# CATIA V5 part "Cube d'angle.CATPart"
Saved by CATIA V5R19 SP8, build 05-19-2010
Part number: Cube d'angle
Bounding box of the stored display mesh (mm): x -5 to 5, y -5 to 5, z -5 to 5
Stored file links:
  D:\Documents\1_Travail\1 - ac-limoges.fr\ac-limoges.fr\Emmanuel Maynard - STI2D_Turgot\1 - IT-I2D\Activités_IT_Première\IT_3_Abris_bus\Maquettes numériques\Abribus_eleve\Cube d'angle.CATPart
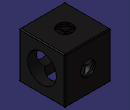
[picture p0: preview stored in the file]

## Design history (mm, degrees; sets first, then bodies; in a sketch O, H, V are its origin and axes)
AxisSystem1: origin (0, 0, 0), X (1, 0, 0), Y (0, 1, 0), Z (0, 0, 1)
Body1 (main body)
  Sketch1 on YZ plane of AxisSystem1, origin (0, 0, 0), H (0, 1, 0), V (0, 0, 1)
    line L1 (5, 5) -> (5, -5)
    line L2 (5, -5) -> (-5, -5)
    line L3 (-5, -5) -> (-5, 5)
    line L4 (-5, 5) -> (5, 5)
    length L2 = 10
    distance L2 L4 = 10
    vertical: L1 V, L3 V
    horizontal: L2 H, L4 H
    equidistance: L1 L3 O, L2 L4 O
  Pad1: profile Sketch1, direction (1, 0, 0), length 5, mirrored extent
  Fillet1: radius 0.2, on face of Pad1 from Sketch1.L3; face of Pad1 from Sketch1.L1; face of Pad1 from Sketch1.L2; start face of Pad1; face of Pad1 from Sketch1.L4
  Sketch2 on end face of Pad1, origin (5, 1.132, -0.2523), H (0, 1, 0), V (0, 0, 1)
    point P1 (-1.132, 0.2523)
    reference projected point E1 (-1.132, 0.2523) from vertex [YZ plane of AxisSystem1 | ZX plane of AxisSystem1 | XY plane of AxisSystem1]
    coincidence: P1 E1
  Hole1: placed by Sketch2, at (5, 0, 0) direction (-1, 0, 0), diameter 3.2, through (limit type 3), type CounterDrilledType, Diameter 3.2, Sketch Sketch2, Profile a sketch, ThreadDepth 10, DiameterThread 11, Pas 1, Diameter 6.2, Angle 90, Depth 8.2
  Sketch3 on face of Pad1 from Sketch1.L2, origin (0.2877, 0.2877, -5), H (1, 0, 0), V (0, -1, 0)
    point P1 (-0.2877, 0.2877)
    reference projected point E1 (-0.2877, 0.2877) from vertex [YZ plane of AxisSystem1 | ZX plane of AxisSystem1 | XY plane of AxisSystem1]
    coincidence: P1 E1
  Hole2: placed by Sketch3, at (0, 0, -5) direction (0, 0, 1), diameter 3.2, through (limit type 3), type CounterDrilledType, Diameter 3.2, Sketch Sketch3, Profile a sketch, ThreadDepth 10, DiameterThread 3.52, Pas 1, Diameter 6.2, Angle 90, Depth 8.2
  Sketch4 on face of Pad1 from Sketch1.L3, origin (0.27, -5, 0.4667), H (1, 0, 0), V (0, 0, 1)
    point P1 (-0.27, -0.4667)
    reference projected point E1 (-0.27, -0.4667) from vertex [YZ plane of AxisSystem1 | ZX plane of AxisSystem1 | XY plane of AxisSystem1]
    coincidence: P1 E1
  Hole3: placed by Sketch4, at (0, -5, 0) direction (0, 1, 0), diameter 3.2, through (limit type 3), type CounterDrilledType, Diameter 3.2, Sketch Sketch4, Profile a sketch, ThreadDepth 10, DiameterThread 3.52, Pas 1, Diameter 6.2, Angle 90, Depth 8.2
